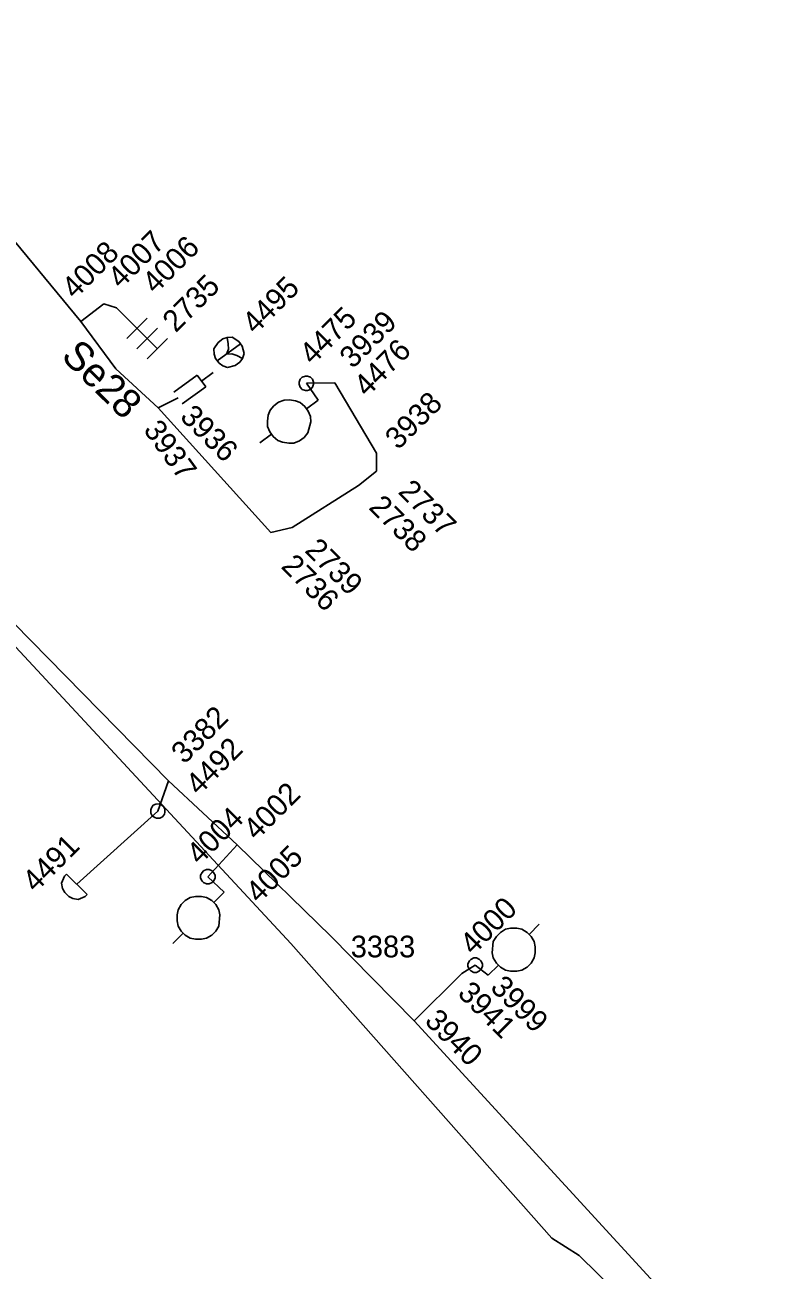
# Model space of a CAD drawing. Extents: x -535557 to -534097, y -1142175 to -1136716.
# Drawn here: x -534999.56 to -534973.32, y -1138864.49 to -1138821.41 of the extents above; entities that cross this region are included whole.
import ezdxf

# ---------------------------------------------------------------- set-up
doc = ezdxf.new("R2010")
doc.units = 0
for name, color, linetype in [('Default', 7, 'Continuous'), ('GIS_vektor_sdelovaci_kabely_CD', 7, 'Continuous'), ('SS_SZDC', 7, 'Continuous')]:
    doc.layers.add(name, color=color, linetype=linetype)

# ---------------------------------------------------------------- blocks, each defined once
blk = doc.blocks.new('POINT_DISPLAY')
at = {"layer": 'Default'}
blk.add_line((0, 0), (0, 0), dxfattribs=at)

msp = doc.modelspace()

# ---------------------------------------------------------------- linework, layer by layer
at = {"layer": 'GIS_vektor_sdelovaci_kabely_CD'}
msp.add_lwpolyline([(-535045.462, -1138783.573), (-535024.919, -1138807.012), (-535025.147, -1138808.084), (-535026.712, -1138809.655), (-535028.973, -1138811.759), (-535019.653, -1138821.946), (-535013.243, -1138828.352), (-535004.947, -1138836.978), (-535003.244, -1138839.172), (-535001.501, -1138841.015), (-535000.173, -1138842.612), (-534990.361, -1138853.189), (-534981.326, -1138863.381), (-534980.378, -1138863.98), (-534973.325, -1138870.913)], dxfattribs=at)
at = {"layer": 'SS_SZDC'}
for p, q in [((-534997.619, -1138831.67), (-535002.59, -1138825.709)), ((-534997.619, -1138831.67), (-534996.829, -1138831.059)), ((-534996.829, -1138831.059), (-534996.39, -1138831.2)), ((-534996.39, -1138831.2), (-534994.975, -1138832.614)), ((-534996.409, -1138833.309), (-534997.619, -1138831.67)), ((-534995.329, -1138831.553), (-534996.036, -1138832.26)), ((-534994.975, -1138831.907), (-534995.682, -1138832.614)), ((-534994.622, -1138832.26), (-534995.329, -1138832.967)), ((-534992.877, -1138832.396), (-534992.716, -1138832.278)), ((-534992.716, -1138832.278), (-534992.565, -1138832.229)), ((-534992.565, -1138832.229), (-534992.385, -1138832.22)), ((-534992.527, -1138832.449), (-534992.565, -1138832.229)), ((-534992.385, -1138832.22), (-534992.156, -1138832.362)), ((-534993.019, -1138832.625), (-534992.877, -1138832.396)), ((-534993.01, -1138832.805), (-534993.019, -1138832.625)), ((-534992.097, -1138832.443), (-534992.902, -1138833.036)), ((-534992.58, -1138832.799), (-534992.519, -1138832.629)), ((-534992.519, -1138832.629), (-534992.527, -1138832.449)), ((-534992.156, -1138832.362), (-534992.038, -1138832.523)), ((-534992.038, -1138832.523), (-534991.97, -1138832.784)), ((-534992.961, -1138832.956), (-534993.01, -1138832.805)), ((-534992.843, -1138833.117), (-534992.961, -1138832.956)), ((-534992.714, -1138833.208), (-534992.843, -1138833.117)), ((-534992.58, -1138832.799), (-534992.4, -1138832.79)), ((-534992.4, -1138832.79), (-534992.23, -1138832.852)), ((-534992.122, -1138833.083), (-534992.283, -1138833.201)), ((-534992.23, -1138832.852), (-534992.031, -1138832.954)), ((-534992.031, -1138832.954), (-534992.122, -1138833.083)), ((-534991.97, -1138832.784), (-534992.031, -1138832.954)), ((-534996.409, -1138833.309), (-534994.949, -1138834.659)), ((-534994.406, -1138834.117), (-534993.597, -1138833.529)), ((-534993.597, -1138833.529), (-534993.304, -1138833.934)), ((-534993.45, -1138833.732), (-534993.046, -1138833.438)), ((-534992.544, -1138833.269), (-534992.714, -1138833.208)), ((-534992.283, -1138833.201), (-534992.544, -1138833.269)), ((-534989.961, -1138833.597), (-534989.855, -1138833.562)), ((-534989.855, -1138833.562), (-534989.784, -1138833.562)), ((-534989.784, -1138833.562), (-534989.678, -1138833.597)), ((-534993.304, -1138833.934), (-534994.113, -1138834.522)), ((-534990.067, -1138833.774), (-534990.032, -1138833.668)), ((-534990.067, -1138833.845), (-534990.067, -1138833.774)), ((-534990.032, -1138833.951), (-534990.067, -1138833.845)), ((-534990.032, -1138833.668), (-534989.961, -1138833.597)), ((-534989.961, -1138834.022), (-534990.032, -1138833.951)), ((-534989.855, -1138834.057), (-534989.961, -1138834.022)), ((-534988.84, -1138833.799), (-534989.819, -1138833.809)), ((-534989.819, -1138833.809), (-534989.409, -1138834.399)), ((-534989.678, -1138834.022), (-534989.784, -1138834.057)), ((-534989.678, -1138833.597), (-534989.607, -1138833.668)), ((-534989.607, -1138833.951), (-534989.678, -1138834.022)), ((-534989.607, -1138833.668), (-534989.572, -1138833.774)), ((-534989.572, -1138833.845), (-534989.607, -1138833.951)), ((-534989.572, -1138833.774), (-534989.572, -1138833.845)), ((-534987.399, -1138836.229), (-534988.84, -1138833.799)), ((-534994.949, -1138834.659), (-534994.26, -1138834.319)), ((-534990.781, -1138834.469), (-534990.59, -1138834.392)), ((-534990.59, -1138834.392), (-534990.409, -1138834.384)), ((-534990.409, -1138834.384), (-534990.2, -1138834.418)), ((-534990.2, -1138834.418), (-534990.031, -1138834.48)), ((-534989.784, -1138834.057), (-534989.855, -1138834.057)), ((-534989.409, -1138834.399), (-534989.814, -1138834.693)), ((-534991.05, -1138838.969), (-534994.949, -1138834.659)), ((-534991.137, -1138834.913), (-534991.075, -1138834.744)), ((-534991.075, -1138834.744), (-534990.943, -1138834.586)), ((-534990.943, -1138834.586), (-534990.781, -1138834.469)), ((-534990.031, -1138834.48), (-534989.873, -1138834.612)), ((-534989.873, -1138834.612), (-534989.814, -1138834.693)), ((-534989.814, -1138834.693), (-534989.755, -1138834.774)), ((-534989.755, -1138834.774), (-534989.678, -1138834.965)), ((-534991.171, -1138835.123), (-534991.137, -1138834.913)), ((-534991.163, -1138835.303), (-534991.171, -1138835.123)), ((-534991.086, -1138835.494), (-534991.163, -1138835.303)), ((-534989.671, -1138835.146), (-534989.767, -1138835.524)), ((-534989.678, -1138834.965), (-534989.671, -1138835.146)), ((-534991.028, -1138835.575), (-534991.432, -1138835.869)), ((-534990.969, -1138835.656), (-534991.086, -1138835.494)), ((-534990.811, -1138835.788), (-534990.969, -1138835.656)), ((-534989.899, -1138835.682), (-534990.061, -1138835.8)), ((-534989.767, -1138835.524), (-534989.899, -1138835.682)), ((-534990.642, -1138835.851), (-534990.811, -1138835.788)), ((-534990.432, -1138835.884), (-534990.642, -1138835.851)), ((-534990.252, -1138835.877), (-534990.432, -1138835.884)), ((-534990.061, -1138835.8), (-534990.252, -1138835.877)), ((-534987.399, -1138836.85), (-534987.399, -1138836.229)), ((-534987.399, -1138836.85), (-534988.02, -1138837.35)), ((-534988.02, -1138837.35), (-534990.31, -1138838.799)), ((-535003.689, -1138838.299), (-534994.59, -1138847.559)), ((-534990.31, -1138838.799), (-534991.05, -1138838.969)), ((-534994.59, -1138847.559), (-534994.96, -1138848.61)), ((-534994.59, -1138847.559), (-534992.21, -1138849.78)), ((-534994.96, -1138848.61), (-534997.76, -1138851.139)), ((-534995.206, -1138848.568), (-534995.185, -1138848.501)), ((-534995.204, -1138848.68), (-534995.206, -1138848.568)), ((-534995.185, -1138848.501), (-534995.119, -1138848.41)), ((-534995.119, -1138848.41), (-534995.03, -1138848.365)), ((-534995.03, -1138848.365), (-534994.918, -1138848.363)), ((-534994.918, -1138848.363), (-534994.851, -1138848.384)), ((-534994.851, -1138848.384), (-534994.76, -1138848.45)), ((-534994.76, -1138848.45), (-534994.715, -1138848.539)), ((-534994.713, -1138848.651), (-534994.734, -1138848.718)), ((-534994.715, -1138848.539), (-534994.713, -1138848.651)), ((-534995.159, -1138848.769), (-534995.204, -1138848.68)), ((-534995.068, -1138848.835), (-534995.159, -1138848.769)), ((-534995.001, -1138848.856), (-534995.068, -1138848.835)), ((-534994.889, -1138848.854), (-534995.001, -1138848.856)), ((-534994.8, -1138848.809), (-534994.889, -1138848.854)), ((-534994.734, -1138848.718), (-534994.8, -1138848.809)), ((-534992.21, -1138849.78), (-534993.229, -1138850.879)), ((-534992.21, -1138849.78), (-534988.979, -1138852.94)), ((-534998.115, -1138850.788), (-534998.186, -1138850.859)), ((-534997.404, -1138851.491), (-534998.115, -1138850.788)), ((-534993.479, -1138850.829), (-534993.429, -1138850.729)), ((-534993.429, -1138850.729), (-534993.379, -1138850.679)), ((-534993.379, -1138850.679), (-534993.279, -1138850.629)), ((-534993.279, -1138850.629), (-534993.179, -1138850.629)), ((-534993.179, -1138850.629), (-534993.079, -1138850.679)), ((-534993.079, -1138850.679), (-534993.029, -1138850.729)), ((-534993.029, -1138850.729), (-534992.979, -1138850.829)), ((-534998.186, -1138850.859), (-534998.29, -1138851.108)), ((-534998.29, -1138851.108), (-534998.254, -1138851.284)), ((-534993.479, -1138850.929), (-534993.479, -1138850.829)), ((-534993.429, -1138851.029), (-534993.479, -1138850.929)), ((-534993.379, -1138851.079), (-534993.429, -1138851.029)), ((-534993.279, -1138851.129), (-534993.379, -1138851.079)), ((-534993.179, -1138851.129), (-534993.279, -1138851.129)), ((-534993.229, -1138850.879), (-534992.67, -1138851.42)), ((-534993.079, -1138851.079), (-534993.179, -1138851.129)), ((-534993.029, -1138851.029), (-534993.079, -1138851.079)), ((-534992.979, -1138850.929), (-534993.029, -1138851.029)), ((-534992.979, -1138850.829), (-534992.979, -1138850.929)), ((-534998.254, -1138851.284), (-534998.182, -1138851.425)), ((-534998.182, -1138851.425), (-534998.04, -1138851.566)), ((-534998.04, -1138851.566), (-534997.898, -1138851.635)), ((-534997.898, -1138851.635), (-534997.721, -1138851.67)), ((-534997.721, -1138851.67), (-534997.474, -1138851.562)), ((-534997.474, -1138851.562), (-534997.404, -1138851.491)), ((-534994.013, -1138851.702), (-534993.836, -1138851.596)), ((-534993.836, -1138851.596), (-534993.659, -1138851.561)), ((-534993.659, -1138851.561), (-534993.447, -1138851.561)), ((-534993.447, -1138851.561), (-534993.271, -1138851.596)), ((-534993.271, -1138851.596), (-534993.094, -1138851.702)), ((-534992.67, -1138851.42), (-534993.023, -1138851.773)), ((-534994.296, -1138852.197), (-534994.26, -1138852.021)), ((-534994.26, -1138852.021), (-534994.154, -1138851.844)), ((-534994.154, -1138851.844), (-534994.013, -1138851.702)), ((-534993.094, -1138851.702), (-534993.023, -1138851.773)), ((-534993.023, -1138851.773), (-534992.952, -1138851.844)), ((-534992.952, -1138851.844), (-534992.846, -1138852.021)), ((-534992.846, -1138852.021), (-534992.811, -1138852.197)), ((-534994.296, -1138852.409), (-534994.296, -1138852.197)), ((-534994.26, -1138852.586), (-534994.296, -1138852.409)), ((-534992.811, -1138852.197), (-534992.846, -1138852.586)), ((-534982.115, -1138852.875), (-534981.762, -1138852.522)), ((-534994.084, -1138852.834), (-534994.437, -1138853.187)), ((-534994.154, -1138852.763), (-534994.26, -1138852.586)), ((-534994.013, -1138852.904), (-534994.154, -1138852.763)), ((-534993.836, -1138853.01), (-534994.013, -1138852.904)), ((-534993.094, -1138852.904), (-534993.271, -1138853.01)), ((-534992.952, -1138852.763), (-534993.094, -1138852.904)), ((-534992.846, -1138852.586), (-534992.952, -1138852.763)), ((-534986.09, -1138855.87), (-534988.979, -1138852.94)), ((-534983.353, -1138853.123), (-534983.247, -1138852.946)), ((-534983.247, -1138852.946), (-534983.105, -1138852.805)), ((-534983.105, -1138852.805), (-534982.928, -1138852.699)), ((-534982.928, -1138852.699), (-534982.752, -1138852.663)), ((-534982.752, -1138852.663), (-534982.54, -1138852.663)), ((-534982.54, -1138852.663), (-534982.363, -1138852.699)), ((-534982.363, -1138852.699), (-534982.186, -1138852.805)), ((-534982.186, -1138852.805), (-534982.045, -1138852.946)), ((-534982.045, -1138852.946), (-534981.939, -1138853.123)), ((-534993.659, -1138853.046), (-534993.836, -1138853.01)), ((-534993.447, -1138853.046), (-534993.659, -1138853.046)), ((-534993.271, -1138853.01), (-534993.447, -1138853.046)), ((-534983.388, -1138853.512), (-534983.353, -1138853.123)), ((-534981.939, -1138853.123), (-534981.903, -1138853.3)), ((-534981.903, -1138853.3), (-534981.903, -1138853.512)), ((-534984.229, -1138853.89), (-534984.179, -1138853.79)), ((-534984.179, -1138853.79), (-534984.129, -1138853.74)), ((-534984.129, -1138853.74), (-534984.029, -1138853.69)), ((-534984.029, -1138853.69), (-534983.929, -1138853.69)), ((-534983.929, -1138853.69), (-534983.829, -1138853.74)), ((-534983.829, -1138853.74), (-534983.779, -1138853.79)), ((-534983.779, -1138853.79), (-534983.729, -1138853.89)), ((-534983.353, -1138853.688), (-534983.388, -1138853.512)), ((-534983.247, -1138853.865), (-534983.353, -1138853.688)), ((-534981.939, -1138853.688), (-534982.045, -1138853.865)), ((-534981.903, -1138853.512), (-534981.939, -1138853.688)), ((-534984.439, -1138854.229), (-534986.09, -1138855.87)), ((-534984.439, -1138854.229), (-534983.979, -1138853.94)), ((-534984.229, -1138853.99), (-534984.229, -1138853.89)), ((-534984.179, -1138854.09), (-534984.229, -1138853.99)), ((-534984.129, -1138854.14), (-534984.179, -1138854.09)), ((-534984.029, -1138854.19), (-534984.129, -1138854.14)), ((-534983.929, -1138854.19), (-534984.029, -1138854.19)), ((-534983.979, -1138853.94), (-534983.529, -1138854.29)), ((-534983.829, -1138854.14), (-534983.929, -1138854.19)), ((-534983.779, -1138854.09), (-534983.829, -1138854.14)), ((-534983.729, -1138853.99), (-534983.779, -1138854.09)), ((-534983.729, -1138853.89), (-534983.729, -1138853.99)), ((-534983.529, -1138854.29), (-534983.176, -1138853.936)), ((-534983.176, -1138853.936), (-534983.247, -1138853.865)), ((-534983.105, -1138854.007), (-534983.176, -1138853.936)), ((-534982.928, -1138854.113), (-534983.105, -1138854.007)), ((-534982.752, -1138854.148), (-534982.928, -1138854.113)), ((-534982.54, -1138854.148), (-534982.752, -1138854.148)), ((-534982.363, -1138854.113), (-534982.54, -1138854.148)), ((-534982.186, -1138854.007), (-534982.363, -1138854.113)), ((-534982.045, -1138853.865), (-534982.186, -1138854.007)), ((-534986.09, -1138855.87), (-534976.22, -1138866.62))]:
    msp.add_line(p, q, dxfattribs=at)

# ---------------------------------------------------------------- block references
for p in [(-534996.829, -1138831.059), (-534996.39, -1138831.2), (-534997.619, -1138831.67), (-534992.5, -1138832.739), (-534996.409, -1138833.309), (-534989.819, -1138833.809), (-534989.819, -1138833.809), (-534988.84, -1138833.799), (-534994.26, -1138834.319), (-534989.409, -1138834.399), (-534994.949, -1138834.659), (-534987.399, -1138836.229), (-534987.399, -1138836.85), (-534988.02, -1138837.35), (-534991.05, -1138838.969), (-534990.31, -1138838.799), (-534994.59, -1138847.559), (-534994.96, -1138848.61), (-534994.96, -1138848.61), (-534992.21, -1138849.78), (-534997.76, -1138851.139), (-534993.229, -1138850.879), (-534993.229, -1138850.879), (-534992.67, -1138851.42), (-534988.979, -1138852.94), (-534984.439, -1138854.229), (-534983.979, -1138853.94), (-534983.979, -1138853.94), (-534983.529, -1138854.29), (-534986.09, -1138855.87)]:
    msp.add_blockref('POINT_DISPLAY', p, dxfattribs=at)

# ---------------------------------------------------------------- texts
for s, height, rotation, p in [('4007', 0.75, 45, (-534996.24, -1138830.569)), ('4006', 0.75, 45, (-534995.046, -1138830.748)), ('4008', 0.75, 45, (-534997.831, -1138830.931)), ('2735', 0.75, 45, (-534994.342, -1138832.085)), ('4495', 0.75, 45, (-534991.587, -1138832.148)), ('4475', 0.75, 45, (-534989.605, -1138833.205)), ('3939', 0.75, 45, (-534988.216, -1138833.335)), ('4476', 0.75, 45, (-534987.727, -1138834.313)), ('Se28', 1, 315.3757, (-534998.346, -1138832.92)), ('3938', 0.75, 45, (-534986.643, -1138836.141)), ('3936', 0.75, 315, (-534994.229, -1138835.01)), ('3937', 0.75, 306, (-534995.483, -1138835.427)), ('2737', 0.75, 315, (-534986.679, -1138837.597)), ('2738', 0.75, 315, (-534987.692, -1138838.133)), ('2739', 0.75, 315, (-534989.912, -1138839.623)), ('2736', 0.75, 315, (-534990.732, -1138840.175)), ('3382', 0.75, 45, (-534994.042, -1138847.014)), ('4492', 0.75, 45, (-534993.542, -1138848.1)), ('4002', 0.75, 45, (-534991.549, -1138849.654)), ('4004', 0.75, 45, (-534993.512, -1138850.504)), ('4491', 0.75, 45, (-534999.192, -1138851.453)), ('4005', 0.75, 45, (-534991.462, -1138851.834)), ('4000', 0.75, 45, (-534984.053, -1138853.622)), ('3941', 0.75, 315, (-534984.622, -1138854.955)), ('3999', 0.75, 315, (-534983.493, -1138854.752)), ('3940', 0.75, 315, (-534985.762, -1138855.911))]:
    msp.add_text(s, height=height, rotation=rotation, dxfattribs=at).set_placement(p)
msp.add_text('3383', height=0.75, dxfattribs=at).set_placement((-534988.285, -1138853.67))

doc.saveas('drawing.dxf')
